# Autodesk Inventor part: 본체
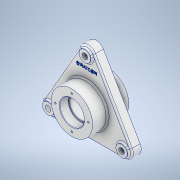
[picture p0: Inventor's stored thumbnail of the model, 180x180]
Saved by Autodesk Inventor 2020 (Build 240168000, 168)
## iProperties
Created: 2023-04
Part Number: 본체
Material: Aluminum 6061
Document SubType Name: Modeling
Designer: home
Density: 2.7 g/cm^3
Appearance: Aluminum - Flat
Mass: 1219.03 g
Surface Area: 640.875 cm^2
Volume: 451.494 cm^3
Author: home
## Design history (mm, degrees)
sketch "Sketch1"
  geometry: L1 (-23.5, -23)-(-23.5, -6); L2 (-23.5, -6)-(-21, -6); L3 (0, -23)-(-40, -23); L4 (-40, -23)-(-40, -5); L5 (-21, -6)-(-21, 30); L6 (0, -23)-(0, 47); L7 (-21, 30)-(-23.5, 30); L8 (-40, 18)-(-40, 47); L9 (-23.5, 30)-(-23.5, 47); L10 (-40, 47)-(0, 47); L11 (-40, -5)-(-45, -5); L12 (-45, 18)-(-40, 18); L13 (-45, -5)-(-45, 18); 2 further points
  constraints: 26 end point, 10 perpendicular, 4 point on line, 1 horizontal, 1 midpoint, 1 vertical, 1 vertical alignment
  dimensions: "d0" = 23 distance of L11.end L12.start; "d1" = 18 distance between parallel lines of L3 L11; "d2" = 70 distance between parallel lines of L3 L10; "d3" = 80 diameter of L8 L6; "d4" = 80 diameter of L4 L6; "d5" = 90 diameter of L13 L6; "d6" = 47 diameter of L9 L6; "d7" = 42 diameter of L5 L6; "d8" = 17 distance of L7.end L9.end; "d9" = 17 distance of L1.start L1.end; "d11" = 5 vertical distance of L11.end point (0, 0)
revolve "Revolution1" sketch "Sketch1" stored, may be unused: angle "d12" = 90 deg
sketch "Sketch2"
  geometry: L1 (0, 82)-(-71.014, -41); L2 (-71.014, -41)-(71.014, -41); L3 (0, 82)-(71.014, -41); L4 (71.014, -57)-(-71.014, -57); L5 (-84.87, -33)-(-13.856, 90); L6 (13.856, 90)-(84.87, -33); C1 r 21 at (0, 0) reference; C2 r 5.5 at (0, 82); C3 r 5.5 at (-71.014, -41); C4 r 5.5 at (71.014, -41); A1 r 82 centre (0, 0) between (0, 82) and (-71.014, -41); A2 r 16 centre (0, 82) between (13.856, 90) and (-13.856, 90); A3 r 16 centre (-71.014, -41) between (-84.87, -33) and (-71.014, -57); A4 r 16 centre (71.014, -41) between (71.014, -57) and (84.87, -33); 1 further point
  constraints: 12 end point, 8 point on circle, 7 centre point, 6 tangent, 2 equal radius, 1 coincident, 1 horizontal, 1 vertical alignment, 9 other
  dimensions: "d13" = 164 diameter of A1; "d14" = 11 diameter of C2; "d17" = 360 deg dimension on point (0, 0) L1.start (derived); "d19" = 16 distance between parallel lines of L3 L6; "d20" = 16 radius of A2
extrude "Extrusion1" join sketch "Sketch2" distance "d21" = 18; taper "d22" = 0 deg
sketch "Sketch3"
  geometry: L1 (155.885, 24)-(84.87, 147) reference; L2 (57.158, 147)-(-13.856, 24) reference; L3 (0, 0)-(142.028, 0) reference; C1 r 5.5 at (71.014, 139) reference; C2 r 5.5 at (71.014, 139) reference; C3 r 5.5 at (0, 16) reference; C4 r 5.5 at (142.028, 16) reference; C5 r 40 at (71.014, 57) reference; C6 r 5.5 at (71.014, 139) reference; C7 r 11 at (71.014, 139); C8 r 11 at (0, 16); C9 r 11 at (142.028, 16); A1 r 16 centre (71.014, 139) between (84.87, 147) and (57.158, 147) reference; A2 r 16 centre (0, 16) between (-13.856, 24) and (0, 0) reference; A3 r 16 centre (142.028, 16) between (142.028, 0) and (155.885, 24) reference; 1 further point
  constraints: 3 centre point, 1 coincident, 7 other
  dimensions: "d23" = 22 diameter of C7; "d26" = 360 deg dimension on point (71.014, 57) C7.centre (derived)
extrude "Extrusion2" join sketch "Sketch3" distance "d28" = 4; taper "d29" = 0 deg
sketch "Sketch4" dims "d30" = 64
  geometry: 6 further points
  constraints: 2 vertical alignment, 1 coincident, 7 other
  dimensions: "d33" = 360 deg dimension on point (0, 0) point (0, 32) (derived)
hole "Hole1" sketch "Sketch4" at (0, 32), (-32, 0), (0, -32), (32, 0) diameter "d35" = 3.242; stored, may be unused: countersink angle "d39" = 90 deg, drill point angle "d41" = 118 deg; dims "d36" = 8, "d37" = 4, "d38" = 2, "d40" = 10
workplane "Work Plane1"
mirror "Mirror1"
chamfer "Chamfer1" distance "d43" = 1; stored, may be unused: second distance "d44" = 2, angle "d45" = 45 deg
fillet "Fillet1" dims "d42" = 0.6
fillet "Fillet2" dims "d46" = 3
fillet "Fillet3" dims "d47" = 3
sketch "Sketch5"
  geometry: 2 further points
  constraints: 1 vertical alignment, 1 other
  dimensions: "d48" = 60 distance of point (65.818, 114) point (65.818, 54)
emboss "Emboss1" sketch "Sketch5" dims "d13" = 164, "d14" = 11, "d17" = 360 deg (derived), "d19" = 16, "d20" = 16, "d49" = 0.5, "d50" = 0
body "Solid1"
node "Projected Loop1"
